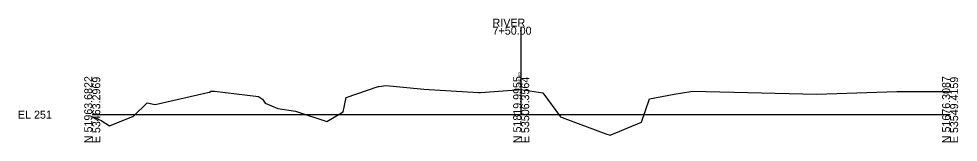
# Model space of a CAD drawing. Extents: x 5628 to 5956, y 92469 to 104012.
# Drawn here: x 5627.6 to 5956.2, y 96968.9 to 97012.3 of the extents above; entities that cross this region are included whole.
import ezdxf

# ---------------------------------------------------------------- set-up
doc = ezdxf.new("R2010")
doc.units = 0
for name, color, linetype in [('Level 10', 7, 'Continuous'), ('Level 60', 7, 'Continuous'), ('Level 63', 7, 'Continuous')]:
    doc.layers.add(name, color=color, linetype=linetype)

msp = doc.modelspace()

# ---------------------------------------------------------------- linework, layer by layer
at = {"layer": 'Level 60'}
for p, q in [((5675.3, 96982.11), (5694.21, 96986.47)), ((5694.21, 96986.47), (5694.58, 96986.47)), ((5694.58, 96986.47), (5694.73, 96986.83)), ((5694.73, 96986.83), (5695.3, 96986.82)), ((5695.3, 96986.82), (5696.05, 96986.82)), ((5696.05, 96986.82), (5711.53, 96984.94)), ((5742.17, 96984.68), (5753.35, 96988.54)), ((5753.35, 96988.54), (5753.7, 96988.43)), ((5753.7, 96988.43), (5756.06, 96988.89)), ((5756.06, 96988.89), (5758.55, 96988.6)), ((5758.55, 96988.6), (5769.28, 96987.53)), ((5769.28, 96987.53), (5788.4, 96986.37)), ((5788.4, 96986.37), (5789.1, 96986.34)), ((5789.1, 96986.34), (5803.34, 96987.44)), ((5803.34, 96987.44), (5810.96, 96986.32)), ((5810.96, 96986.32), (5817.08, 96977.84)), ((5856.84, 96985.76), (5862.67, 96986.72)), ((5862.67, 96986.72), (5863.17, 96986.83)), ((5863.17, 96986.83), (5906.76, 96985.85)), ((5906.76, 96985.85), (5934.72, 96986.7)), ((5934.72, 96986.7), (5952.39, 96986.76)), ((5952.39, 96986.76), (5953.34, 96986.62)), ((5667.71, 96978.08), (5672.5, 96982.73)), ((5672.5, 96982.73), (5675.3, 96982.11)), ((5711.53, 96984.94), (5712.84, 96984.08)), ((5712.84, 96984.08), (5713.75, 96982.65)), ((5713.75, 96982.65), (5718.21, 96980.72)), ((5741.05, 96979.59), (5742.17, 96984.68)), ((5845.39, 96975.98), (5848.21, 96984.19)), ((5848.21, 96984.19), (5856.84, 96985.76)), ((5718.21, 96980.72), (5724.39, 96979.78)), ((5724.39, 96979.78), (5735.43, 96976.22)), ((5735.43, 96976.22), (5741.05, 96979.59)), ((5653.34, 96977.9), (5656.43, 96976.56)), ((5656.43, 96976.56), (5659.39, 96974.71)), ((5659.39, 96974.71), (5667.71, 96978.08)), ((5817.08, 96977.84), (5817.66, 96977.59)), ((5817.66, 96977.59), (5832.99, 96971.89)), ((5834.41, 96971.44), (5845.39, 96975.98)), ((5832.99, 96971.89), (5834.41, 96971.44))]:
    msp.add_line(p, q, dxfattribs=at)
at = {"layer": 'Level 63'}
for p, q in [((5803.34, 96978.6), (5803.34, 97009.49)), ((5653.34, 96978.6), (5803.34, 96978.6)), ((5803.34, 96978.6), (5953.34, 96978.6))]:
    msp.add_line(p, q, dxfattribs=at)

# ---------------------------------------------------------------- texts
at = {"layer": 'Level 10'}
msp.add_text('255.42', height=1.2, rotation=90, dxfattribs=at).set_placement((5803.54, 96988.44))
at = {"layer": 'Level 63'}
for s, p in [('RIVER', (5793.34, 97009.49)), ('7+50.00', (5793.34, 97006.69)), ('EL 251', (5627.34, 96977.2))]:
    msp.add_text(s, height=2.8, dxfattribs=at).set_placement(p)
for s, p in [('N 51963.6822', (5653.34, 96968.6)), ('E 53463.2969', (5656.14, 96968.6)), ('N 51819.9955', (5803.34, 96968.6)), ('E 53506.3564', (5806.14, 96968.6)), ('N 51676.3087', (5953.34, 96968.6)), ('E 53549.4159', (5956.14, 96968.6))]:
    msp.add_text(s, height=2.8, rotation=90, dxfattribs=at).set_placement(p)

doc.saveas('drawing.dxf')
